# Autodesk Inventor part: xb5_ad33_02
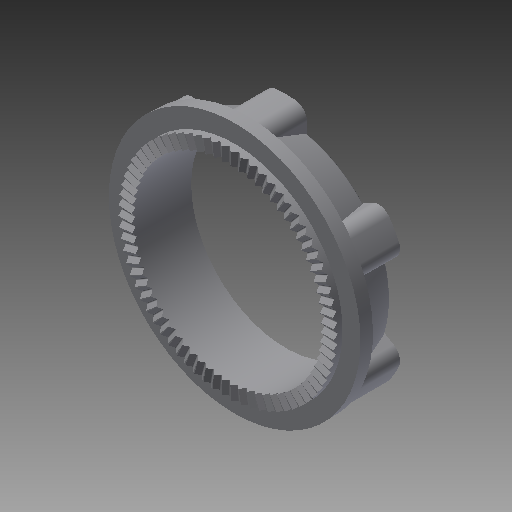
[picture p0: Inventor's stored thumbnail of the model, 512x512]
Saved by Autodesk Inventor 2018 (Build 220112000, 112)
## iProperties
Company: TraceParts S.A.
Created: 2018-05
Part Number: xb5_ad33_02
Checked By: TraceParts S.A.
Material: Generic
Catalog Web Link: www.traceparts.com
Document SubType Name: Modeling
Designer: TraceParts
Density: 1 g/cm^3
Appearance: Default
Author: TraceParts
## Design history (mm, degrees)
feature "xb5_ad33_02.ipt"
body "Solid1"
